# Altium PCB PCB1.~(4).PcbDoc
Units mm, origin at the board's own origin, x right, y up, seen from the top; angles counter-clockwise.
Board outline 25 x 17 mm, 2 copper layers (Top Layer, Bottom Layer); 9 components, 6 nets, 20 pads, 0 vias.
Unrouted connection lines stored in the file: 14.
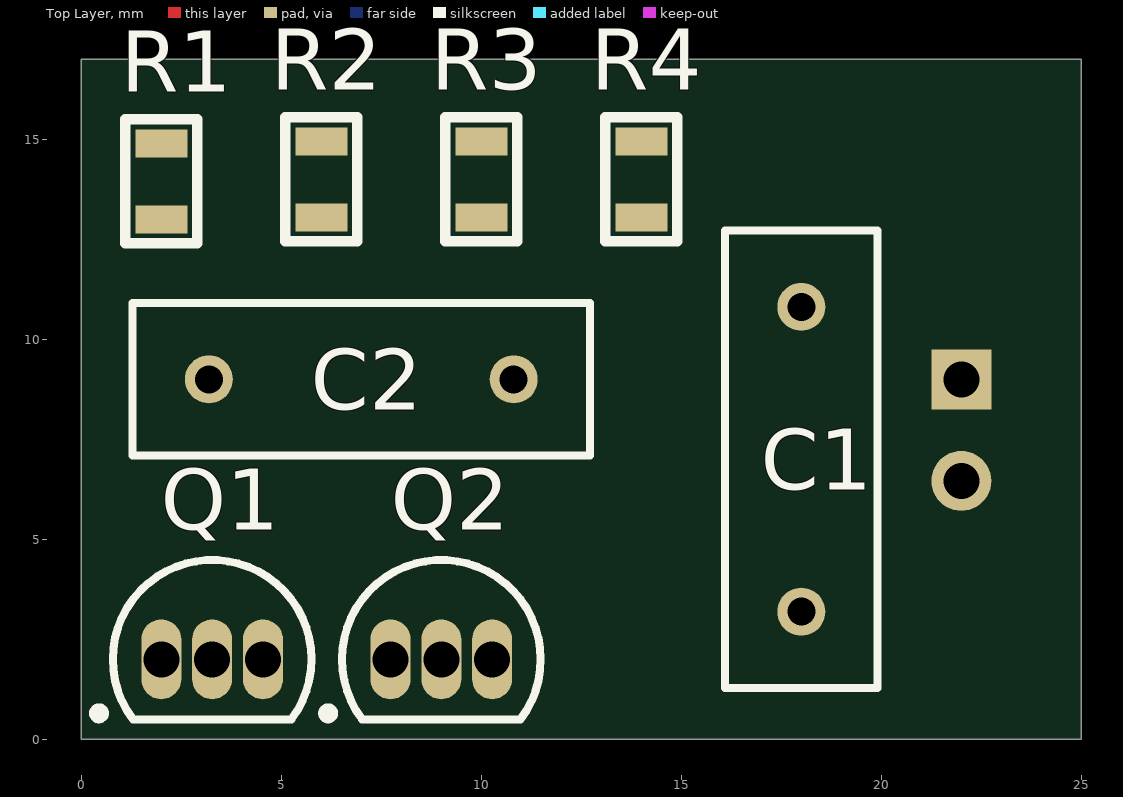
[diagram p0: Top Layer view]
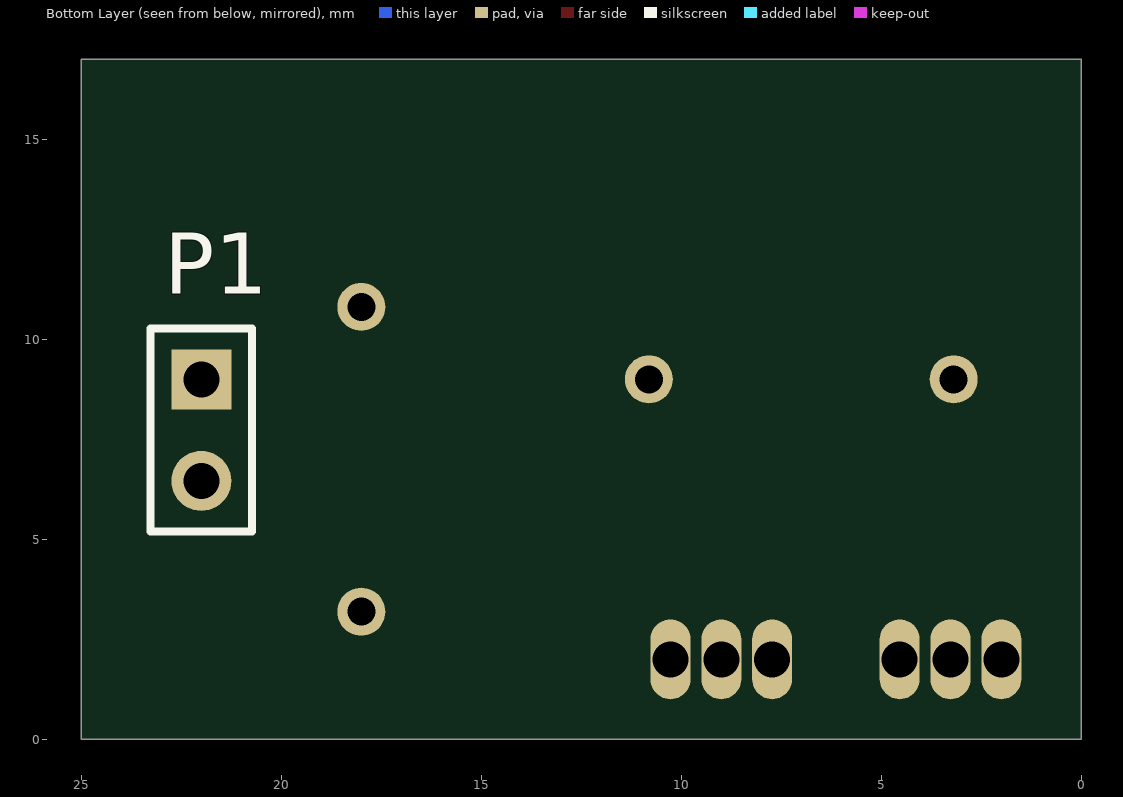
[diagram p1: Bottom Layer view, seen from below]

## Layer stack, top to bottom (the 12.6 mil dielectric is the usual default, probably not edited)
Top Solder: solder mask 0.0102, Solder Resist, Dk 3.5
Top Layer: signal copper 0.0356
Dielectric 1: dielectric 0.32, FR-4, Dk 4.8
Bottom Layer: signal copper 0.0356
Bottom Solder: solder mask 0.0102, Solder Resist, Dk 3.5

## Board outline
0,0 25,0 25,17 0,17

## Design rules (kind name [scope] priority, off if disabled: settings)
Clearance [All] p1: gap=0.254 ignorepadtopadclearanceinfootprint=FALSE except(0.3: Arc-Arc Arc-Track Track-Track)
PolygonConnect [All] p1: connectstyle=Relief reliefconductorwidth=0.254 reliefentries=4 polygonreliefangle="90 Angle" airgapwidth=0.254
RoutingVias [All] p1: holewidth=0.6 width=1 viastyle="Through Hole" minholewidth=0.4 minwidth=0.7 maxholewidth=0.711 maxwidth=1.27
SolderMaskExpansion [All] p1: expansion=0.102 istentingtop=FALSE
Width [All] p1: maxlimit=1 minlimit=0.1 preferedwidth=0.254
30 further rules are at their usual default settings.

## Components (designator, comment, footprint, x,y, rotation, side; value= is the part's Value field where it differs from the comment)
C1 "Cap" RAD-0.3 18,7 r90 top value=100pF
C2 "Cap" RAD-0.3 7,9 r0 top value=100pF
P1 "Header 2" HDR1X2 22,9 r270 bottom
Q1 "2N3904" TO-92A 3.27,2 r270 top
Q2 "2N3904" TO-92A 9,2 r270 top
R1 "Res" "Res 0805" 2,13.95 r90 top
R2 "Res" "Res 0805" 6,14 r90 top
R3 "Res" "Res 0805" 10,14 r90 top
R4 "Res" "Res 0805" 14,14 r90 top

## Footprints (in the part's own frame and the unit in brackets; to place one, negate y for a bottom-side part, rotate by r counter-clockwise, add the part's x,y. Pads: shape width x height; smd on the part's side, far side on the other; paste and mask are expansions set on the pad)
HDR1X2 [mm] "Connector; Header; 2 Position"
  rect 1.5x1.5 hole 0.9: 1(0,0)
  round 1.5 hole 0.9: 2(2.54,0)
  silkscreen extent -1.27,-1.27 3.81,1.27
RAD-0.3 [mm] "Radial Cap, Thru-Hole; 2 Leads; 0.3 in Pin Spacing"
  round 1.2 hole 0.7: 1(-3.81,0) 2(3.81,0)
  silkscreen extent -5.71,-1.91 5.71,1.91
"Res 0805" [mm]
  rect 0.7x1.3 smd: 1(-0.95,0) 2(0.95,0)
  silkscreen extent -1.55,-0.9 1.55,0.9
TO-92A [mm] "TO, Flat Index; 3 In-Line, Axial Leads; Body Dia. 4.5mm; Leads 0.51 x 0.48 mm (max)"
  oval 2x1 hole 0.9: 1(0,-1.27) 2(0,0) 3(0,1.27)
  silkscreen extent -2.48,-2.95 1.5,2.48, body extent -2.48,-2.5 1.5,2.5, height 6.86

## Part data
C1 C2: "Capacitor"
P1: "Header, 2-Pin"
Q1 Q2: "NPN General Purpose Amplifier"

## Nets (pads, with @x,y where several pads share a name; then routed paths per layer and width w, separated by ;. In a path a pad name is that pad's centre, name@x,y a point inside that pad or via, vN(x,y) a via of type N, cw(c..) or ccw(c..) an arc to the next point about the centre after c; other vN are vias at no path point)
+12V: P1.1 R1.2 R2.2 R3.2 R4.2
GND: P1.2 Q1.1 Q2.1
NetC1_1: C1.1 Q1.2 R1.1
NetC1_2: C1.2 Q2.3 R3.1
NetC2_1: C2.1 Q1.3 R2.1
NetC2_2: C2.2 Q2.2 R4.1

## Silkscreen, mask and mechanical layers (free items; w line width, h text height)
Mechanical 1:
  the board outline again, w0.254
